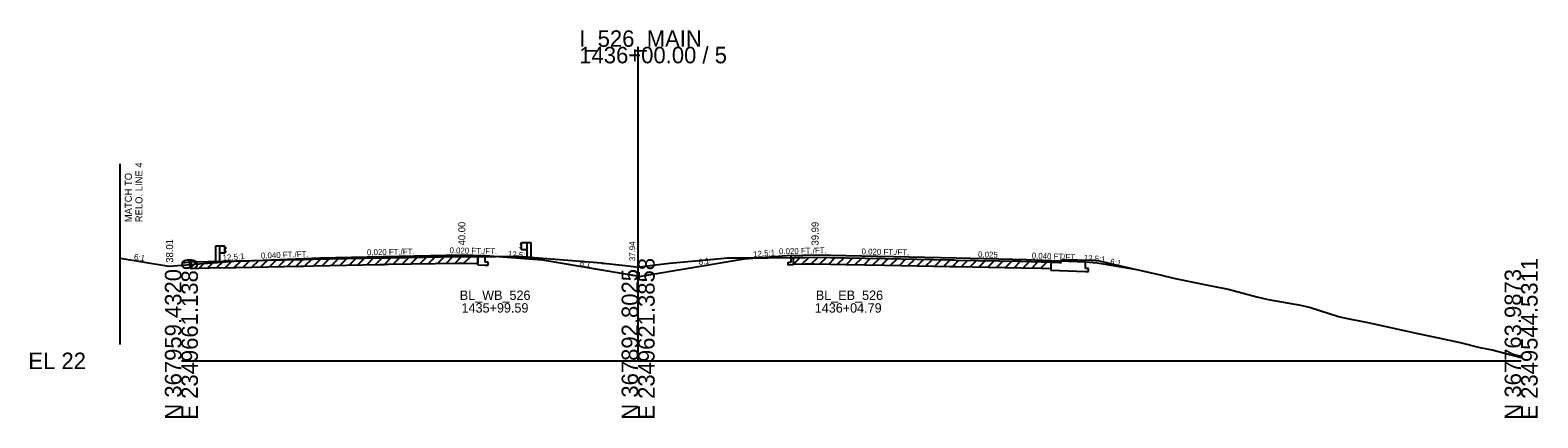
# Model space of a CAD drawing. Extents: x -170 to 2527928, y -10 to 1619750.
# Drawn here: x 4974.3 to 5230.4, y 1990.3 to 2056.2 of the extents above; entities that cross this region are included whole.
import ezdxf

# ---------------------------------------------------------------- set-up
doc = ezdxf.new("R2010")
doc.units = 0
for name, color, linetype in [('RD_GPK_XS_Cell', 7, 'Continuous'), ('RD_XS_Base', 7, 'Continuous'), ('RD_XS_EarthShd', 7, 'Continuous'), ('RD_XS_ExGround', 7, 'Continuous'), ('RD_XS_ExPaveRet', 7, 'Continuous'), ('RD_XS_GR', 7, 'Continuous'), ('RD_XS_MatchLine', 7, 'Continuous'), ('RD_XS_Pave', 7, 'Continuous'), ('RD_XS_PaveShd', 7, 'Continuous'), ('RD_XS_TieSlope', 7, 'Continuous'), ('RD_XS_TX_Elev_EX', 7, 'Continuous'), ('RD_XS_TX_Slope', 7, 'Continuous'), ('RD_XS_TX_Station', 7, 'Continuous')]:
    doc.layers.add(name, color=color, linetype=linetype)

msp = doc.modelspace()

# ---------------------------------------------------------------- linework, layer by layer
at = {"layer": 'RD_GPK_XS_Cell'}
for p, q in [((5077.59, 2000), (5077.59, 2053.37)), ((5000, 2000), (5077.59, 2000)), ((5077.59, 2000), (5227.59, 2000))]:
    msp.add_line(p, q, dxfattribs=at)
at = {"layer": 'RD_XS_Base'}
for p, q in [((5050.38, 2016.31), (5050.38, 2017.67)), ((5050.38, 2016.31), (5051.59, 2016.28)), ((5051.59, 2016.78), (5051.59, 2017.92)), ((5052.09, 2016.77), (5051.59, 2016.78)), ((5051.59, 2016.28), (5052.09, 2016.27)), ((5052.09, 2016.27), (5052.09, 2016.77)), ((5103.09, 2016.77), (5103.59, 2016.78)), ((5103.09, 2016.27), (5103.09, 2016.77)), ((5103.97, 2016.29), (5103.09, 2016.27)), ((5103.59, 2016.78), (5103.59, 2017.91)), ((5103.97, 2016.29), (5103.97, 2017.56)), ((5147.69, 2017.05), (5147.69, 2015.41)), ((5153.59, 2015.68), (5153.59, 2016.81)), ((5154.09, 2015.67), (5153.59, 2015.68)), ((5154.09, 2015.17), (5154.09, 2015.67)), ((5147.69, 2015.41), (5153.59, 2015.18)), ((5153.59, 2015.18), (5154.09, 2015.17))]:
    msp.add_line(p, q, dxfattribs=at)
at = {"layer": 'RD_XS_EarthShd'}
for p, q in [((5007.56, 2016.79), (4997.88, 2016.02)), ((5009.72, 2016.96), (5007.56, 2016.79)), ((5051.59, 2017.92), (5061.34, 2017.14)), ((5103.59, 2017.91), (5095.59, 2017.27))]:
    msp.add_line(p, q, dxfattribs=at)
at = {"layer": 'RD_XS_ExGround'}
msp.add_lwpolyline([(5000, 2016.71), (5000.56, 2016.74), (5001.24, 2016.76), (5001.34, 2016.8), (5001.49, 2016.84), (5004.48, 2016.91), (5004.8, 2016.91), (5009.26, 2017), (5020.12, 2017.22), (5020.85, 2017.24), (5022.4, 2017.27), (5033.64, 2017.5), (5034.56, 2017.52), (5035.1, 2017.53), (5047.05, 2017.72), (5048.16, 2017.71), (5050.38, 2017.67), (5056.53, 2017.78), (5057.26, 2017.79), (5057.77, 2017.75), (5071.34, 2016.63), (5071.46, 2016.62), (5071.69, 2016.6), (5075.41, 2016.18), (5077.66, 2015.93), (5077.82, 2015.95), (5082.92, 2016.59), (5090.45, 2017.3), (5092.79, 2017.51), (5098.55, 2017.51), (5099.6, 2017.5), (5103.97, 2017.56), (5105.97, 2017.58), (5107.52, 2017.6), (5112.87, 2017.51), (5119.44, 2017.4), (5130.51, 2017.16), (5131.2, 2017.14), (5131.6, 2017.13), (5142.59, 2016.93), (5146.13, 2016.85), (5147.69, 2016.81), (5147.85, 2016.77), (5147.89, 2016.76), (5149.18, 2016.73), (5149.43, 2016.74), (5149.58, 2017.14), (5149.61, 2017.22), (5149.95, 2017.23), (5150.01, 2017.23), (5154.48, 2017.13), (5155.33, 2017.11), (5155.69, 2017.06), (5158.52, 2016.37), (5166.28, 2014.61), (5168.81, 2014.01), (5174.91, 2012.75), (5177.84, 2012.19), (5182.71, 2010.87), (5184.62, 2010.43), (5190.09, 2009.46), (5191.78, 2009.04), (5196.58, 2007.51), (5197.8, 2007.26), (5201.53, 2006.5), (5210.53, 2004.56), (5210.78, 2004.51), (5210.86, 2004.49), (5211.13, 2004.43), (5217.24, 2003.12), (5220.58, 2002.27), (5222.67, 2001.87), (5227.59, 2000.58)], dxfattribs=at)
at = {"layer": 'RD_XS_ExPaveRet'}
for p, q in [((5001.49, 2015.72), (5002.63, 2016.87)), ((5001.49, 2015.72), (5001.49, 2016.84)), ((5001.49, 2015.72), (5004.48, 2015.79)), ((5002.99, 2015.75), (5004.13, 2016.9)), ((5004.48, 2015.79), (5004.8, 2015.79)), ((5004.49, 2015.79), (5005.63, 2016.93)), ((5004.8, 2015.79), (5009.26, 2015.88)), ((5005.99, 2015.82), (5007.13, 2016.96)), ((5007.49, 2015.85), (5008.63, 2016.99)), ((5008.99, 2015.88), (5010.13, 2017.02)), ((5009.26, 2015.88), (5020.12, 2016.1)), ((5010.49, 2015.91), (5011.63, 2017.05)), ((5011.99, 2015.94), (5013.13, 2017.08)), ((5013.49, 2015.96), (5014.63, 2017.11)), ((5014.99, 2015.99), (5016.13, 2017.14)), ((5016.49, 2016.02), (5017.63, 2017.17)), ((5017.99, 2016.05), (5019.13, 2017.2)), ((5019.49, 2016.08), (5020.63, 2017.23)), ((5020.12, 2016.1), (5020.85, 2016.11)), ((5020.85, 2016.11), (5022.4, 2016.15)), ((5020.99, 2016.12), (5022.14, 2017.27)), ((5022.4, 2016.15), (5033.64, 2016.38)), ((5022.49, 2016.16), (5023.63, 2017.3)), ((5023.99, 2016.19), (5025.13, 2017.33)), ((5025.49, 2016.22), (5026.63, 2017.36)), ((5026.99, 2016.25), (5028.13, 2017.39)), ((5028.49, 2016.28), (5029.63, 2017.42)), ((5029.99, 2016.31), (5031.13, 2017.45)), ((5031.49, 2016.34), (5032.63, 2017.48)), ((5032.99, 2016.37), (5034.13, 2017.51)), ((5033.64, 2016.38), (5034.56, 2016.4)), ((5034.49, 2016.4), (5035.62, 2017.54)), ((5034.56, 2016.4), (5035.1, 2016.41)), ((5035.1, 2016.41), (5047.05, 2016.6)), ((5035.99, 2016.42), (5037.13, 2017.56)), ((5037.49, 2016.45), (5038.63, 2017.59)), ((5038.99, 2016.47), (5040.13, 2017.61)), ((5040.49, 2016.49), (5041.63, 2017.63)), ((5041.99, 2016.52), (5043.13, 2017.66)), ((5043.49, 2016.54), (5044.63, 2017.68)), ((5044.99, 2016.57), (5046.13, 2017.71)), ((5046.49, 2016.59), (5047.61, 2017.72)), ((5047.05, 2016.6), (5048.16, 2016.59)), ((5047.99, 2016.59), (5049.09, 2017.69)), ((5048.16, 2016.59), (5050.38, 2016.55)), ((5050.38, 2017.67), (5050.38, 2016.55)), ((5103.97, 2016.44), (5105.1, 2017.57)), ((5103.97, 2016.44), (5103.97, 2017.56)), ((5103.97, 2016.44), (5105.97, 2016.46)), ((5105.47, 2016.46), (5106.6, 2017.59)), ((5105.97, 2016.46), (5107.52, 2016.48)), ((5106.97, 2016.47), (5108.09, 2017.59)), ((5107.52, 2016.48), (5112.87, 2016.39)), ((5108.47, 2016.46), (5109.57, 2017.56)), ((5109.97, 2016.44), (5111.07, 2017.54)), ((5111.47, 2016.41), (5112.57, 2017.52)), ((5112.87, 2016.39), (5119.44, 2016.28)), ((5112.97, 2016.39), (5114.07, 2017.49)), ((5114.47, 2016.36), (5115.57, 2017.46)), ((5115.97, 2016.34), (5117.07, 2017.44)), ((5117.47, 2016.31), (5118.57, 2017.41)), ((5118.97, 2016.29), (5120.07, 2017.39)), ((5119.44, 2016.28), (5130.51, 2016.04)), ((5120.47, 2016.26), (5121.57, 2017.35)), ((5121.97, 2016.22), (5123.07, 2017.32)), ((5123.47, 2016.19), (5124.57, 2017.29)), ((5124.97, 2016.16), (5126.07, 2017.25)), ((5126.47, 2016.12), (5127.57, 2017.22)), ((5127.97, 2016.09), (5129.07, 2017.19)), ((5129.47, 2016.06), (5130.57, 2017.15)), ((5130.51, 2016.04), (5131.2, 2016.02)), ((5130.97, 2016.02), (5132.07, 2017.13)), ((5131.2, 2016.02), (5131.6, 2016.01)), ((5131.6, 2016.01), (5142.59, 2015.81)), ((5132.47, 2016), (5133.57, 2017.1)), ((5133.97, 2015.97), (5135.07, 2017.07)), ((5135.47, 2015.94), (5136.57, 2017.04)), ((5136.97, 2015.92), (5138.07, 2017.02)), ((5138.47, 2015.89), (5139.57, 2016.99)), ((5139.97, 2015.86), (5141.07, 2016.96)), ((5141.47, 2015.83), (5142.57, 2016.93)), ((5142.59, 2015.81), (5146.13, 2015.73)), ((5142.97, 2015.8), (5144.07, 2016.9)), ((5144.47, 2015.77), (5145.57, 2016.87)), ((5145.97, 2015.73), (5147.06, 2016.83)), ((5146.13, 2015.73), (5147.69, 2015.69)), ((5147.69, 2016.81), (5147.69, 2015.69))]:
    msp.add_line(p, q, dxfattribs=at)
at = {"layer": 'RD_XS_GR'}
for p, q in [((5006.47, 2019.47), (5005.81, 2019.47)), ((5005.81, 2019.47), (5005.81, 2016.67)), ((5007.39, 2019.47), (5006.47, 2019.47)), ((5006.47, 2019.47), (5006.47, 2016.73)), ((5007.39, 2018.3), (5006.47, 2018.3)), ((5007.39, 2018.3), (5007.39, 2019.47)), ((5007.39, 2019.4), (5007.56, 2019.2)), ((5007.56, 2019.15), (5007.39, 2018.95)), ((5007.56, 2018.63), (5007.39, 2018.83)), ((5007.39, 2018.38), (5007.56, 2018.58)), ((5007.56, 2019.2), (5007.56, 2019.15)), ((5007.56, 2018.58), (5007.56, 2018.63)), ((5057.75, 2020.03), (5057.59, 2019.83)), ((5057.59, 2019.83), (5057.59, 2019.78)), ((5057.59, 2019.78), (5057.75, 2019.58)), ((5057.59, 2019.26), (5057.75, 2019.46)), ((5057.59, 2019.21), (5057.59, 2019.26)), ((5057.75, 2019.01), (5057.59, 2019.21)), ((5057.75, 2018.94), (5057.75, 2020.1)), ((5057.75, 2020.1), (5058.67, 2020.1)), ((5057.75, 2018.94), (5058.67, 2018.94)), ((5058.67, 2020.1), (5059.34, 2020.1)), ((5058.67, 2020.1), (5058.67, 2017.36)), ((5059.34, 2020.1), (5059.34, 2017.31))]:
    msp.add_line(p, q, dxfattribs=at)
at = {"layer": 'RD_XS_MatchLine'}
msp.add_line((4989.59, 2002.79), (4989.59, 2033.46), dxfattribs=at)
at = {"layer": 'RD_XS_Pave'}
for p, q in [((5023.59, 2017.52), (5047.59, 2018)), ((5107.59, 2017.99), (5131.59, 2017.51)), ((5131.59, 2017.51), (5143.59, 2017.21))]:
    msp.add_line(p, q, dxfattribs=at)
at = {"layer": 'RD_XS_PaveShd'}
for p, q in [((5009.72, 2016.96), (5023.59, 2017.52)), ((5047.59, 2018), (5051.59, 2017.92)), ((5103.59, 2017.91), (5107.59, 2017.99)), ((5143.59, 2017.21), (5153.59, 2016.81))]:
    msp.add_line(p, q, dxfattribs=at)
at = {"layer": 'RD_XS_TieSlope'}
for p, q in [((4997.88, 2016.02), (4989.59, 2017.4)), ((5061.34, 2017.14), (5078.06, 2014.35)), ((5095.59, 2017.27), (5078.06, 2014.35)), ((5153.59, 2016.81), (5155.59, 2016.65)), ((5155.59, 2016.65), (5161.94, 2015.6))]:
    msp.add_line(p, q, dxfattribs=at)

# ---------------------------------------------------------------- texts
at = {"layer": 'RD_GPK_XS_Cell'}
for s, p in [('I_526_MAIN', (5067.59, 2053.37)), ('1436+00.00 / 5', (5067.59, 2050.57)), ('EL 22', (4974, 1998.6))]:
    msp.add_text(s, height=2.8, dxfattribs=at).set_placement(p)
for s, p in [('E 2349661.1389', (5002.8, 1990)), ('E 2349621.3858', (5080.39, 1990)), ('E 2349544.5311', (5230.39, 1990)), ('N 367959.4320', (5000, 1990)), ('N 367892.8025', (5077.59, 1990)), ('N 367763.9873', (5227.59, 1990))]:
    msp.add_text(s, height=2.8, rotation=90, dxfattribs=at).set_placement(p)
at = {"layer": 'RD_XS_TX_Elev_EX'}
msp.add_text('37.94', height=1, rotation=90, dxfattribs=at).set_placement((5077.09, 2016.94))
at = {"layer": 'RD_XS_TX_Slope'}
for s, rotation, p in [('12.5:1', 4.5739, (5007.05, 2017.01)), ('0.040 FT./FT.', 2.2906, (5013.53, 2017.37)), ('0.020 FT./FT.', 1.1458, (5031.53, 2017.93)), ('0.020 FT./FT.', 358.8542, (5045.54, 2018.29)), ('12.5:1', 355.4261, (5055.42, 2017.69)), ('12.5:1', 4.5739, (5097.17, 2017.62)), ('0.020 FT./FT.', 1.1458, (5101.53, 2018.12)), ('0.020 FT./FT.', 358.8542, (5115.54, 2018.09)), ('0.025', 358.5679, (5135.33, 2017.6)), ('0.040 FT/FT', 357.7094, (5144.44, 2017.4)), ('6:1', 350.5377, (4991.88, 2017.23)), ('6:1', 350.5377, (5067.63, 2016.17)), ('6:1', 9.4623, (5087.92, 2016.28)), ('12.5:1', 355.4261, (5153.26, 2017.04)), ('6:1', 346.8379, (5157.7, 2016.45))]:
    msp.add_text(s, height=1, rotation=rotation, dxfattribs=at).set_placement(p)
at = {"layer": 'RD_XS_TX_Station'}
for s, p in [('RELO. LINE 4', (4993.39, 2023.56)), ('MATCH TO', (4991.59, 2023.56)), (' 40.00', (5048.24, 2019.17)), (' 39.99', (5108.24, 2019.17)), ('38.01', (4998.6, 2016.68))]:
    msp.add_text(s, height=1.2, rotation=90, dxfattribs=at).set_placement(p)
for s, p in [('BL_WB_526', (5047.29, 2010.35)), ('BL_EB_526', (5107.78, 2010.35)), ('1435+99.59', (5047.59, 2008.2)), ('1436+04.79', (5107.59, 2008.19))]:
    msp.add_text(s, height=1.6, dxfattribs=at).set_placement(p)

doc.saveas('drawing.dxf')
